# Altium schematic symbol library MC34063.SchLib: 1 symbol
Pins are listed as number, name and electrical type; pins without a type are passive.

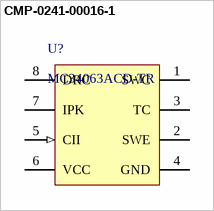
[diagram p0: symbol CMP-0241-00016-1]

## CMP-0241-00016-1
designator U?, comment MC34063ACD-TR
DC/DC converter control circuit, 8-Pin SO, Tape and Reel
footprint SO8_L (SOIC, 8-Leads, Body 4.9x3.9mm, Pitch 1.27mm, IPC High Density)
footprint SO8_N (SOIC, 8-Leads, Body 4.9x3.9mm, Pitch 1.27mm, IPC Medium Density)
footprint SO8_M (SOIC, 8-Leads, Body 4.9x3.9mm, Pitch 1.27mm, IPC Low Density)
pins: 1 SWC (oc), 2 SWE (oe), 3 TC, 4 GND (power), 5 CII (in), 6 VCC (power), 7 IPK, 8 DRC (oc)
